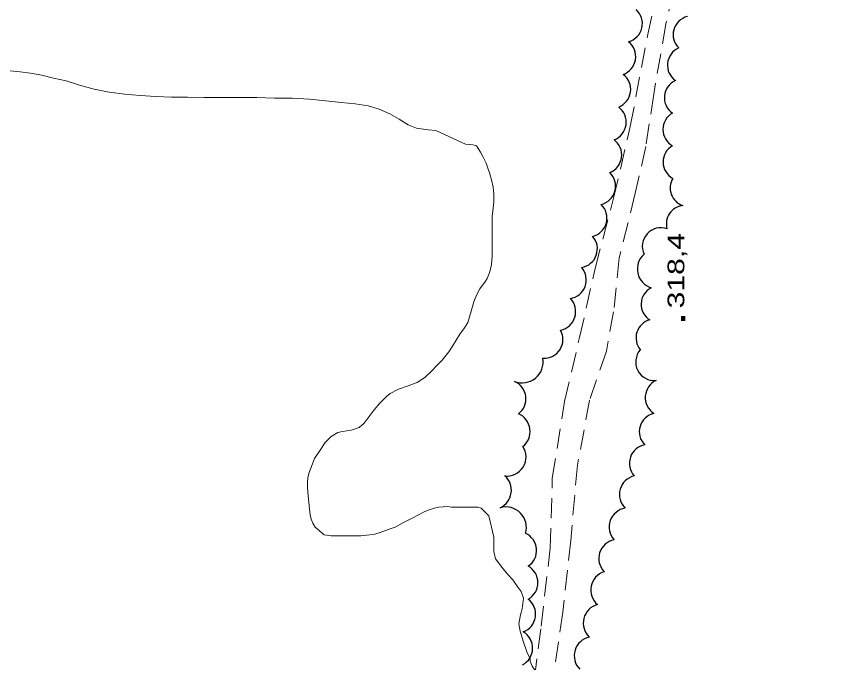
# Model space of a CAD drawing. Extents: x 240591 to 242335, y 5323482 to 5326937.
# Drawn here: x 240765 to 240913.3, y 5324410.4 to 5324526.5 of the extents above; entities that cross this region are included whole.
import ezdxf

# ---------------------------------------------------------------- set-up
doc = ezdxf.new("R2010")
doc.units = 0
doc.header["$LTSCALE"] = 1.2
doc.linetypes.add('LONG_DASHED', pattern=[7.5, 6, -1.5])
doc.linetypes.add('MEDIUM_DASHED', pattern=[4.5, 3, -1.5])
for name, color, linetype, lineweight in [('19', 7, 'Continuous', 13), ('2', 7, 'Continuous', 13), ('3', 7, 'Continuous', 140), ('44', 7, 'Continuous', 25)]:
    doc.layers.add(name, color=color, linetype=linetype, lineweight=lineweight)

msp = doc.modelspace()

# ---------------------------------------------------------------- linework, layer by layer
at = {"layer": '19', "linetype": 'MEDIUM_DASHED'}
for points in [[(240857.3, 5324402.1), (240859.2, 5324416.9), (240860.8, 5324430.9), (240861.2, 5324443.5), (240863.4, 5324457.3), (240866.1, 5324468.8), (240868.9, 5324481.2), (240872.2, 5324493.8), (240875.2, 5324506.7), (240878.3, 5324523), (240881.4, 5324537.5), (240884.2, 5324551.3), (240885.6, 5324563.2), (240886.5, 5324575.7), (240887.5, 5324589.9), (240889.5, 5324604.4), (240891.1, 5324616.8), (240893.2, 5324629.9), (240894.2, 5324637.3), (240894.2, 5324640.7), (240892.3, 5324642.5), (240889.6, 5324644.5)], [(240938.5, 5324566.7), (240926.7, 5324563.8), (240914.6, 5324560.3), (240905.6, 5324557.4), (240896.5, 5324554.2), (240891, 5324551.1), (240886.9, 5324545.1), (240884, 5324536.2), (240881.6, 5324525.1), (240879.4, 5324512.5), (240878, 5324503.1), (240876.1, 5324494.7), (240873.2, 5324483.1), (240872.2, 5324473.4), (240870.9, 5324466.3), (240867.9, 5324457.5), (240865.7, 5324445.8), (240864.5, 5324432.3), (240863.1, 5324419.4), (240861.1, 5324406.3)]]:
    msp.add_lwpolyline(points, dxfattribs=at)
at = {"layer": '2', "linetype": 'LONG_DASHED'}
for points in [[(240840.3, 5324506), (240838.9, 5324506.1), (240836.8, 5324506.4), (240835.3, 5324507), (240833.7, 5324508), (240832, 5324509), (240830.1, 5324509.8), (240828.1, 5324510.4), (240825.8, 5324510.8), (240823.3, 5324511), (240820.5, 5324511.3), (240817.6, 5324511.6), (240814.5, 5324511.8), (240811.3, 5324511.8), (240808.1, 5324511.9), (240804.9, 5324511.9), (240801.8, 5324511.9), (240798.7, 5324511.9), (240795.7, 5324512), (240792.8, 5324512), (240790, 5324512.1), (240787.2, 5324512.3), (240784.4, 5324512.5), (240781.6, 5324512.9), (240778.9, 5324513.4), (240776.3, 5324514.1), (240773.9, 5324514.9), (240771.6, 5324515.4), (240769.5, 5324515.9), (240767.5, 5324516.3), (240765.6, 5324516.5), (240763.8, 5324516.7)], [(240840.3, 5324506), (240845.6, 5324503.5), (240846.9, 5324503.4), (240847.4, 5324503.3), (240847.6, 5324503.2), (240848.3, 5324502.1), (240848.7, 5324501.3), (240849.3, 5324500.1), (240849.6, 5324499.2), (240850, 5324498.2), (240850.3, 5324497.1), (240850.6, 5324495.8), (240850.7, 5324494.5), (240850.7, 5324493.1), (240850.6, 5324492), (240850.4, 5324490.5), (240850.4, 5324489.5), (240850.4, 5324488.4), (240850.4, 5324487), (240850.4, 5324484.9), (240850.4, 5324483.4), (240850.3, 5324481.9), (240850, 5324480.6), (240849.5, 5324479.4), (240849.2, 5324478.9), (240848.2, 5324477.5), (240847.6, 5324476.4), (240847.1, 5324475.2), (240846.6, 5324473.5), (240846.3, 5324472.5), (240846, 5324471.5), (240845.4, 5324470.5), (240844.6, 5324469.4), (240843.9, 5324468.3), (240843.3, 5324467.2), (240842.6, 5324466.2), (240841.4, 5324464.7), (240840.5, 5324463.8), (240839.5, 5324462.7), (240838.3, 5324461.6), (240836.9, 5324460.7), (240836.1, 5324460.4), (240835.3, 5324460.1), (240833.6, 5324459.5), (240832.1, 5324458.7), (240831.4, 5324458.2), (240830.8, 5324457.6), (240830.2, 5324457), (240829.2, 5324455.8), (240828.3, 5324454.6), (240827.4, 5324453.4), (240826.5, 5324452.6), (240825.1, 5324452.1), (240823.5, 5324451.9), (240822.7, 5324451.7), (240821.5, 5324451), (240820.4, 5324449.9), (240819.5, 5324448.5), (240818.5, 5324447), (240817.8, 5324445.3), (240817.5, 5324444.5), (240817.3, 5324443.6), (240817.2, 5324442.7), (240817.2, 5324441.9), (240817.3, 5324441), (240817.5, 5324438.5), (240817.7, 5324436.9), (240817.9, 5324436.1), (240818.2, 5324435.4), (240818.6, 5324434.7), (240820.2, 5324433.3), (240821.5, 5324433.1), (240822.2, 5324433.1), (240824.3, 5324433.1), (240825.5, 5324433.1), (240826.8, 5324433.1), (240828.4, 5324433.3), (240829.3, 5324433.4), (240830.3, 5324433.7), (240832.1, 5324434.4), (240833, 5324434.7), (240834.5, 5324435.5), (240836, 5324436.3), (240838.3, 5324437.5), (240839.1, 5324437.8), (240840, 5324438.1), (240840.8, 5324438.3), (240842.4, 5324438.4), (240843.1, 5324438.3), (240844.5, 5324438.3), (240845.9, 5324438.3), (240847.8, 5324438.3), (240848.4, 5324438.1), (240849.8, 5324436.7)], [(240849.8, 5324436.7), (240850.7, 5324432.9), (240850.7, 5324431.2), (240850.7, 5324430.3), (240851, 5324429), (240852.4, 5324427.2), (240853.2, 5324426.2), (240854.1, 5324425.2), (240854.9, 5324424.1), (240855.6, 5324423.1), (240856, 5324421.9), (240855.8, 5324420), (240855.5, 5324418.9), (240855.2, 5324417.3), (240855.4, 5324416), (240856, 5324414), (240856.6, 5324412.3), (240856.9, 5324411.6)]]:
    msp.add_lwpolyline(points, dxfattribs=at)
at = {"layer": '2'}
msp.add_lwpolyline([(240858.1, 5324408.4), (240858, 5324409.1), (240857.6, 5324409.7), (240857.2, 5324410.6), (240857.2, 5324411.1), (240856.9, 5324411.6)], dxfattribs=at)
at = {"layer": '3'}
msp.add_line((240884.7, 5324471.8), (240884.7, 5324472.6), dxfattribs=at)
at = {"layer": '44'}
for centre, radius, start, end in [((240871.872, 5324513.351), 3.398, 291.55139, 53.14445), ((240871.068, 5324507.483), 3.397, 290.91016, 52.82963), ((240870.259, 5324501.577), 3.399, 291.77805, 53.51719), ((240869.167, 5324495.98), 3.389, 283.87989, 46.03335), ((240855.758, 5324464.427), 3.802, 248.90013, 9.28076), ((240853.076, 5324457.758), 3.387, 306.9057, 67.1864), ((240881.283, 5324457.981), 3.392, 114.79782, 236.8934), ((240880.198, 5324451.85), 3.378, 103.13874, 224.7837), ((240878.386, 5324446.165), 3.357, 100.06228, 222.20439), ((240876.693, 5324440.562), 3.44, 103.32441, 225.46439), ((240852.843, 5324434.62), 3.696, 343.66076, 105.58701), ((240874.853, 5324434.721), 3.438, 99.59918, 221.78478), ((240872.987, 5324429.059), 3.442, 101.68647, 223.73034), ((240871.552, 5324423.393), 3.451, 107.74602, 229.48501), ((240870.204, 5324417.44), 3.448, 105.02921, 226.7137), ((240868.579, 5324411.568), 3.442, 102.39736, 224.40467)]:
    msp.add_arc(centre, radius, start, end, dxfattribs=at)
for centre, major_axis, ratio, start_param, end_param in [((240873.979, 5324525.193), (-1.013, 3.235), 0.999995, 3.1133106, 5.2457526), ((240886.309, 5324523.197), (-3.307, 0.832), 0.989898, 5.2112168, 7.3170092), ((240872.779, 5324519.275), (-2.638, 2.142), 0.999983, 2.5921508, 4.7202862), ((240885.25, 5324517.711), (-3.36, 0.341), 0.999856, 5.2214542, 7.3467736), ((240884.681, 5324511.866), (-3.328, 0.496), 0.998602, 5.2762945, 7.3979242), ((240884.421, 5324506.175), (-3.355, 0.192), 0.998936, 5.2829936, 7.4044811), ((240884.466, 5324500.322), (-3.375, -0.049), 0.995796, 5.2173809, 7.3405678), ((240885.697, 5324495.633), (1.691, -2.877), 0.997669, 3.6340719, 5.4245865), ((240867.61, 5324490.243), (3.289, -0.885), 0.999949, 5.2213928, 7.3475981), ((240885.006, 5324489.186), (-1.926, -2.725), 0.998686, 3.8713258, 5.5965066), ((240880.683, 5324485.173), (-1.986, -2.678), 0.998038, 3.4397186, 5.7908236), ((240865.889, 5324484.703), (3.174, -1.225), 0.996586, 5.2512226, 7.3726461), ((240880.007, 5324481.086), (-3.543, -0.075), 0.99989, 5.411343, 7.5330295), ((240863.912, 5324479.131), (-0.62, 3.335), 0.999995, 3.1139768, 5.2454779), ((240880.451, 5324474.75), (-3.311, 0.117), 0.996832, 5.2143753, 7.3360617), ((240861.983, 5324473.417), (3.257, -1.008), 0.99991, 5.2184774, 7.3492655), ((240879.556, 5324468.714), (-0.784, -3.244), 0.997243, 3.6364056, 5.6492534), ((240859.696, 5324468.44), (2.378, -2.438), 0.999927, 5.4555651, 7.5833354), ((240879.5, 5324464.375), (1.884, -2.753), 0.997663, 3.3920404, 5.790123), ((240854.016, 5324451.907), (-0.454, 3.338), 0.944951, 3.6349381, 5.7898398), ((240853.262, 5324447.198), (1.472, 3.03), 0.945188, 3.4209966, 5.7912048), ((240850.672, 5324441.293), (0.364, 3.354), 0.93853, 3.6376555, 5.7176477), ((240854.994, 5324430.494), (3.376, 0.272), 0.999994, 5.2224028, 7.348655), ((240855.214, 5324424.713), (3.4, -0.2), 0.998806, 5.2786825, 7.4014423), ((240854.803, 5324419.049), (3.357, -0.495), 0.999796, 5.2159904, 7.3454581), ((240854.257, 5324412.945), (3.395, -0.255), 0.998634, 5.2744232, 7.3946779)]:
    msp.add_ellipse(centre, major_axis=major_axis, ratio=ratio, start_param=start_param, end_param=end_param, dxfattribs=at)

# ---------------------------------------------------------------- texts
at = {"layer": '3', "width": 1.35}
msp.add_text('318,4', height=3, rotation=90, dxfattribs=at).set_placement((240884.9, 5324474))

doc.saveas('drawing.dxf')
